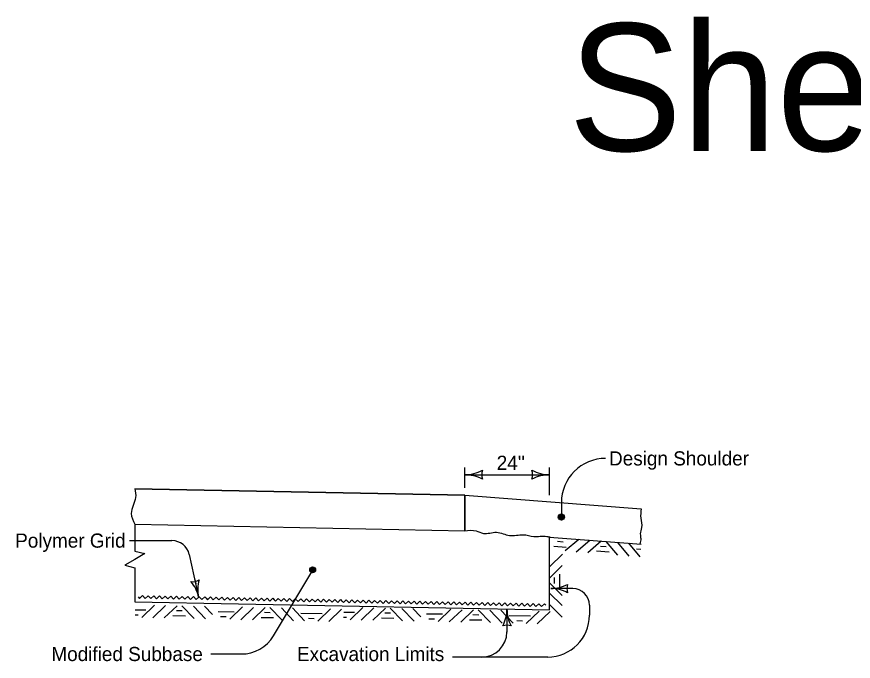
# Model space of a CAD drawing. Extents: x 10028 to 81668, y 6395 to 11634.
# Drawn here: x 14286 to 15231, y 7025 to 7754 of the extents above; entities that cross this region are included whole.
import ezdxf

# ---------------------------------------------------------------- set-up
doc = ezdxf.new("R2010")
doc.units = 0
for name, color, linetype in [('dsnCellElements', 7, 'Continuous'), ('dsnStdTextLabel', 7, 'Continuous'), ('ShtPlotIdentification', 7, 'Continuous')]:
    doc.layers.add(name, color=color, linetype=linetype)

msp = doc.modelspace()

# ---------------------------------------------------------------- linework, layer by layer
at = {"layer": 'ShtPlotIdentification'}
for p, q in [((14792.17, 7221.01), (14792.17, 7243.75)), ((14792.17, 7235.77), (14888.17, 7235.77)), ((14888.17, 7212.44), (14888.17, 7243.75)), ((14792.17, 7212.44), (14419.24, 7219.93)), ((14419.24, 7219.93), (14792.17, 7212.44)), ((14792.17, 7172.44), (14792.17, 7212.44)), ((14792.17, 7212.44), (14792.17, 7172.44)), ((14792.17, 7212.44), (14991.63, 7197.09)), ((14901.41, 7204.21), (14901.41, 7187.83)), ((14419.24, 7179.92), (14792.17, 7172.44)), ((14419.24, 7179.92), (14792.17, 7172.44)), ((14419.24, 7179.66), (14419.24, 7149.4)), ((14413.11, 7161.19), (14461.22, 7161.19)), ((14888.17, 7082.79), (14888.17, 7165.05)), ((14888.17, 7165.05), (14991.63, 7157.09)), ((14921.08, 7162.52), (14905.89, 7149.5)), ((14933.47, 7161.34), (14918.29, 7148.32)), ((14946.46, 7160.56), (14931.28, 7147.55)), ((14951.86, 7160.15), (14964.87, 7144.96)), ((14964.81, 7158.92), (14977.82, 7143.74)), ((14977.24, 7158.19), (14990.26, 7143.01)), ((14419.24, 7149.4), (14430.59, 7146.57)), ((14430.59, 7146.57), (14419.24, 7139.95)), ((14480.76, 7145.5), (14491.36, 7097.37)), ((14888.4, 7131.88), (14902.54, 7146.02)), ((14419.24, 7139.95), (14407.9, 7133.33)), ((14407.9, 7133.33), (14419.24, 7130.49)), ((14888.17, 7118.87), (14902.31, 7133.01)), ((14419.24, 7130.49), (14419.24, 7092.18)), ((14575.97, 7053.72), (14620.27, 7127.83)), ((14486.97, 7117.29), (14488.1, 7112.18)), ((14888.17, 7113.46), (14902.31, 7099.31)), ((14914.31, 7107.05), (14889.58, 7107.05)), ((14888.17, 7101.88), (14902.31, 7087.74)), ((14419.24, 7092.18), (14888.16, 7082.77)), ((14441.51, 7088.16), (14427.09, 7074.31)), ((14453.95, 7087.69), (14439.53, 7073.83)), ((14466.96, 7087.65), (14452.54, 7073.8)), ((14472.37, 7087.54), (14486.23, 7073.12)), ((14485.38, 7087.06), (14499.23, 7072.63)), ((14497.83, 7087.03), (14506.93, 7077.56)), ((14541.04, 7086.17), (14526.62, 7072.31)), ((14553.49, 7085.69), (14539.06, 7071.83)), ((14566.5, 7085.65), (14552.07, 7071.8)), ((14571.91, 7085.55), (14585.76, 7071.12)), ((14584.91, 7085.06), (14598.76, 7070.64)), ((14597.36, 7085.03), (14611.22, 7070.61)), ((14640.58, 7084.17), (14626.15, 7070.31)), ((14653.02, 7083.69), (14638.6, 7069.84)), ((14677.11, 7085.53), (14662.69, 7071.67)), ((14689.56, 7085.05), (14675.13, 7071.19)), ((14702.57, 7085.01), (14688.14, 7071.16)), ((14707.98, 7084.91), (14721.83, 7070.48)), ((14720.98, 7084.42), (14734.83, 7070)), ((14733.43, 7084.4), (14742.53, 7074.92)), ((14776.65, 7083.53), (14762.22, 7069.67)), ((14839.9, 7083.73), (14839.9, 7057.56)), ((14888.17, 7088.82), (14902.31, 7074.68)), ((14933.21, 7088.14), (14933.21, 7076.84)), ((14789.09, 7083.05), (14774.67, 7069.2)), ((14802.1, 7083.02), (14787.68, 7069.16)), ((14807.51, 7082.91), (14821.36, 7068.49)), ((14820.51, 7082.42), (14834.37, 7068)), ((14832.96, 7082.4), (14846.82, 7067.97)), ((14876.18, 7081.53), (14861.75, 7067.67)), ((14888.62, 7081.05), (14874.2, 7067.2)), ((14505.18, 7033.01), (14539.46, 7033.01)), ((14885.94, 7029.57), (14778.18, 7029.57))]:
    msp.add_line(p, q, dxfattribs=at)
for points in [[(14901.14, 7184.61), (14902.32, 7185.15), (14904.15, 7185.71), (14904.51, 7187.58), (14904.26, 7189.22), (14903.08, 7190.73), (14901.34, 7190.57), (14899.49, 7190.31), (14898.61, 7188.85), (14898.45, 7187.3), (14899.53, 7185.27), (14900.88, 7185.1), (14902.72, 7185.57), (14904.23, 7186.75), (14904.18, 7188.49), (14903, 7189.9), (14901.35, 7190.06), (14899.51, 7189.7), (14899.23, 7188.66), (14898.86, 7187.41), (14899.72, 7185.89), (14901.06, 7185.93), (14902.6, 7186.18), (14903.7, 7187.04), (14903.14, 7188.57), (14901.99, 7189.46), (14900.44, 7189.52), (14900.05, 7188.68), (14899.57, 7187.74), (14900.32, 7186.53), (14901.46, 7186.25), (14902.48, 7186.8), (14902.55, 7187.93), (14902.01, 7188.74), (14900.97, 7189.02), (14900.47, 7188.59), (14900.18, 7187.97), (14900.72, 7187.06), (14901.44, 7186.87), (14902.15, 7187.3), (14902.03, 7187.92), (14901.51, 7188.31), (14900.79, 7188.29), (14900.8, 7187.78), (14901.43, 7187.49)], [(14897.09, 7160.5), (14903.6, 7160)], [(14892.82, 7154.96), (14906.97, 7153.87)], [(14941.21, 7149.58), (14955.36, 7148.49)], [(14945.48, 7155.12), (14951.99, 7154.62)], [(14986.37, 7152), (14991.21, 7151.63)], [(14620, 7125.11), (14621.11, 7125.61), (14622.85, 7126.15), (14623.19, 7127.91), (14622.95, 7129.46), (14621.83, 7130.89), (14620.18, 7130.74), (14618.44, 7130.5), (14617.61, 7129.11), (14617.45, 7127.64), (14618.48, 7125.73), (14619.75, 7125.57), (14621.49, 7126.02), (14622.92, 7127.12), (14622.87, 7128.78), (14621.76, 7130.11), (14620.2, 7130.25), (14618.46, 7129.91), (14618.2, 7128.94), (14617.84, 7127.76), (14618.66, 7126.32), (14619.93, 7126.36), (14621.38, 7126.59), (14622.42, 7127.4), (14621.89, 7128.85), (14620.8, 7129.69), (14619.34, 7129.74), (14618.97, 7128.96), (14618.51, 7128.07), (14619.23, 7126.92), (14620.3, 7126.66), (14621.26, 7127.17), (14621.33, 7128.24), (14620.82, 7129.01), (14619.84, 7129.27), (14619.36, 7128.87), (14619.09, 7128.28), (14619.6, 7127.42), (14620.29, 7127.24), (14620.96, 7127.65), (14620.84, 7128.23), (14620.35, 7128.61), (14619.67, 7128.58), (14619.68, 7128.1), (14620.27, 7127.83)], [(14899.52, 7109.07), (14899.52, 7123.26)], [(14893.67, 7112.9), (14893.67, 7119.43)], [(14423.05, 7097.51), (14424.62, 7095.88), (14427.88, 7099.01), (14431.02, 7095.75), (14434.28, 7098.88), (14437.42, 7095.62), (14440.68, 7098.75), (14443.82, 7095.49), (14447.08, 7098.63), (14450.21, 7095.36), (14453.48, 7098.5), (14456.61, 7095.23), (14459.88, 7098.37), (14463.01, 7095.11), (14466.28, 7098.24), (14469.41, 7094.98), (14472.67, 7098.11), (14475.81, 7094.85), (14479.07, 7097.98), (14482.21, 7094.72), (14485.47, 7097.86), (14488.61, 7094.59), (14491.87, 7097.73), (14495.01, 7094.46), (14498.27, 7097.6), (14499.84, 7095.97)], [(14499.84, 7095.97), (14501.4, 7094.34), (14504.67, 7097.47), (14507.8, 7094.21), (14511.07, 7097.34), (14514.2, 7094.08), (14517.47, 7097.21), (14520.6, 7093.95), (14523.86, 7097.09), (14527, 7093.82), (14530.26, 7096.96), (14533.4, 7093.69), (14536.66, 7096.83), (14539.8, 7093.56), (14543.06, 7096.7), (14546.2, 7093.44), (14549.46, 7096.57), (14552.59, 7093.31), (14555.86, 7096.44), (14558.99, 7093.18), (14562.26, 7096.31), (14565.39, 7093.05), (14568.66, 7096.19), (14571.79, 7092.92), (14575.05, 7096.06), (14576.62, 7094.43)], [(14576.62, 7094.43), (14578.19, 7092.79), (14581.45, 7095.93), (14584.59, 7092.67), (14587.85, 7095.8), (14590.99, 7092.54), (14594.25, 7095.67), (14597.39, 7092.41), (14600.65, 7095.54), (14603.78, 7092.28), (14607.05, 7095.42), (14610.18, 7092.15), (14613.45, 7095.29), (14616.58, 7092.02), (14619.84, 7095.16), (14622.98, 7091.89), (14626.24, 7095.03), (14629.38, 7091.77), (14632.64, 7094.9), (14635.78, 7091.64), (14639.04, 7094.77), (14642.18, 7091.51), (14645.44, 7094.64), (14648.57, 7091.38), (14651.84, 7094.52), (14653.41, 7092.88)], [(14653.44, 7092.78), (14655.01, 7091.15), (14658.27, 7094.29), (14661.41, 7091.02), (14664.67, 7094.16), (14667.81, 7090.89), (14671.07, 7094.03), (14674.2, 7090.77), (14677.47, 7093.9), (14680.6, 7090.64), (14683.87, 7093.77), (14687, 7090.51), (14690.27, 7093.64), (14693.4, 7090.38), (14696.66, 7093.52), (14699.8, 7090.25), (14703.06, 7093.39), (14706.2, 7090.12), (14709.46, 7093.26), (14712.6, 7090), (14715.86, 7093.13), (14719, 7089.87), (14722.26, 7093), (14725.39, 7089.74), (14728.66, 7092.87), (14730.23, 7091.24)], [(14730.23, 7091.24), (14731.79, 7089.61), (14735.06, 7092.75), (14738.19, 7089.48), (14741.45, 7092.62), (14744.59, 7089.35), (14747.85, 7092.49), (14750.99, 7089.23), (14754.25, 7092.36), (14757.39, 7089.1), (14760.65, 7092.23), (14763.79, 7088.97), (14767.05, 7092.1), (14770.18, 7088.84), (14773.45, 7091.97), (14776.58, 7088.71), (14779.85, 7091.85), (14782.98, 7088.58), (14786.25, 7091.72), (14789.38, 7088.45), (14792.64, 7091.59), (14795.78, 7088.33), (14799.04, 7091.46), (14802.18, 7088.2), (14805.44, 7091.33), (14807.01, 7089.7)], [(14807.01, 7089.7), (14808.58, 7088.07), (14811.84, 7091.2), (14814.98, 7087.94), (14818.24, 7091.08), (14821.37, 7087.81), (14824.64, 7090.95), (14827.77, 7087.68), (14831.04, 7090.82), (14834.17, 7087.56), (14837.44, 7090.69), (14840.57, 7087.43), (14843.83, 7090.56), (14846.97, 7087.3), (14850.23, 7090.43), (14853.37, 7087.17), (14856.63, 7090.31), (14859.77, 7087.04), (14863.03, 7090.18), (14866.17, 7086.91), (14869.43, 7090.05), (14872.56, 7086.78), (14875.83, 7089.92), (14878.96, 7086.66), (14882.23, 7089.79), (14883.79, 7088.16)], [(14419.68, 7077.32), (14422.94, 7077.26)], [(14419.79, 7083.12), (14431.82, 7082.88)], [(14462.35, 7076.39), (14476.54, 7076.1)], [(14466.29, 7082.17), (14472.83, 7082.04)], [(14513.29, 7081.25), (14531.35, 7080.88)], [(14515.94, 7075.39), (14522.47, 7075.26)], [(14561.88, 7074.39), (14576.07, 7074.11)], [(14565.83, 7080.17), (14572.36, 7080.04)], [(14606.83, 7079.37), (14630.89, 7078.89)], [(14655.28, 7074.69), (14658.54, 7074.62)], [(14655.4, 7080.49), (14667.42, 7080.24)], [(14701.9, 7079.53), (14708.43, 7079.4)], [(14748.89, 7078.61), (14766.96, 7078.25)], [(14801.43, 7077.53), (14807.96, 7077.4)], [(14842.43, 7076.73), (14866.49, 7076.25)], [(14615.48, 7073.39), (14622.01, 7073.26)], [(14697.95, 7073.75), (14712.14, 7073.47)], [(14751.55, 7072.75), (14758.08, 7072.62)], [(14797.48, 7071.75), (14811.67, 7071.47)], [(14851.08, 7070.76), (14857.61, 7070.63)]]:
    msp.add_lwpolyline(points, dxfattribs=at)
for centre, radius in [((14901.41, 7187.83), 3.5), ((14620.26, 7128.15), 3.31)]:
    msp.add_circle(centre, radius, dxfattribs=at)
for centre, radius, start, end in [((14951.41, 7204.21), 50, 90, 180), ((14792.17, 7278.27), 42.5, 270, 298.07249), ((14792.17, 7193.27), 42.5, 61.92751, 90), ((14827.8, 7235.77), 16.42, 162.26665, 197.73335), ((14852.53, 7235.77), 16.42, 342.26665, 17.73335), ((14888.17, 7278.27), 42.5, 241.92751, 270), ((14852.53, 7235.77), 16.42, 342.26665, 17.73335), ((14888.17, 7278.27), 42.5, 241.92751, 270), ((14888.17, 7193.27), 42.5, 90, 118.07249), ((14888.17, 7193.27), 42.5, 90, 118.07249), ((14461.22, 7141.19), 20, 12.43134, 90), ((14484.12, 7130.27), 15.52, 264.68499, 300.15169), ((14452.13, 7088.73), 40.18, 12.41834, 40.49083), ((14530.6, 7106.01), 40.18, 164.34585, 192.41834), ((14889.59, 7147.23), 40.18, 270, 298.07249), ((14889.59, 7147.23), 40.18, 270, 298.07249), ((14923.27, 7107.05), 15.52, 162.26665, 197.73335), ((14923.27, 7107.05), 15.52, 162.26665, 197.73335), ((14889.59, 7066.87), 40.18, 61.92751, 90), ((14889.59, 7066.87), 40.18, 61.92751, 90), ((14914.31, 7088.14), 18.91, 0, 90), ((14799.72, 7083.73), 40.18, 331.92751, 360), ((14880.07, 7083.73), 40.18, 180, 208.07249), ((14885.95, 7076.84), 47.27, 270, 360), ((14839.9, 7050.05), 15.52, 72.26665, 107.73335), ((14811.54, 7057.93), 28.36, 270, 360), ((14539.46, 7075.55), 42.54, 270, 329.12488)]:
    msp.add_arc(centre, radius, start, end, dxfattribs=at)
for points in [[(14419.24, 7219.93), (14420.06, 7209.91), (14415.18, 7191.87), (14419.24, 7179.92)], [(14419.24, 7219.93), (14420.06, 7209.91), (14415.18, 7191.87), (14419.24, 7179.92)], [(14991.63, 7197.09), (14991.15, 7186.57), (14992.11, 7176.05), (14990.68, 7168.88), (14991.15, 7163.62), (14990.2, 7157.4)], [(14792.17, 7172.44), (14805.12, 7172.23), (14813.25, 7169.36), (14828.07, 7170.79), (14842.9, 7166.96), (14858.2, 7167.92), (14870.16, 7166.01), (14884.98, 7166.01), (14888.81, 7165.05)]]:
    msp.add_spline(points, degree=3, dxfattribs=at)

# ---------------------------------------------------------------- texts
at = {"layer": 'dsnCellElements'}
for s, p in [('Design Shoulder', (14955.33, 7246.21)), ("24''", (14828.3, 7241.24)), ('Polymer Grid', (14283.96, 7153.26)), ('Modified Subbase', (14324.88, 7025.01)), ('Excavation Limits', (14602.53, 7025.01))]:
    msp.add_text(s, height=16, dxfattribs=at).set_placement(p)
at = {"layer": 'dsnStdTextLabel'}
msp.add_text('Sheet 2', height=144, dxfattribs=at).set_placement((14909.31, 7602.02))

doc.saveas('drawing.dxf')
